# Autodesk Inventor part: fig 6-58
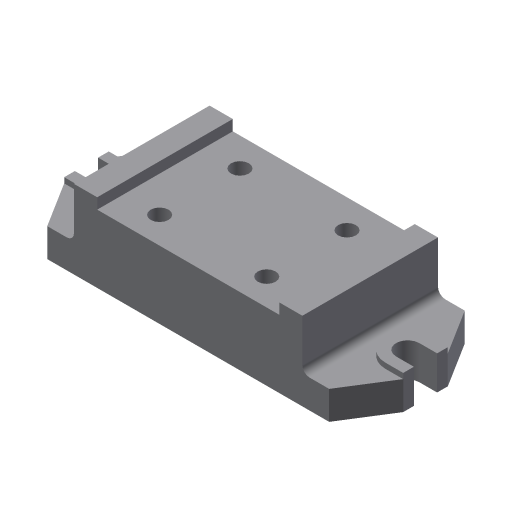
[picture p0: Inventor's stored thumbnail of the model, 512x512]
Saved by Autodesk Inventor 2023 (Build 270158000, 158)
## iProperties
Created: 2001-12
Part Number: fig 6-58
Document SubType Name: Modeling
Designer: Renu Muthoo
Density: 1 g/cm^3
Material: Generic
Appearance: Default
Control State: 0
Master: False
Checked Out: False
Shininess: 77.0
Angle Display Precision: 2
Document Length Units: 11269
Document Angle Units: 11279
Document Time Units: 11290
Document Mass Units: 11283
Document Length Units Precision: 3
Document Angle Units Precision: 2
Density: 0.0
Volumn: 0.0
Area: 0.0
PropertySet Name: Model Information
Author: Renu Muthoo
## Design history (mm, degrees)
sketch "Sketch3"
  geometry: L1 (-59.119, -24.322)-(-59.119, 19.678); L2 (-59.119, 19.678)-(-46.119, 19.678); L3 (-46.119, 19.678)-(-46.119, 13.678); L4 (-46.119, 13.678)-(55.881, 13.678); L5 (55.881, 13.678)-(55.881, 19.678); L6 (55.881, 19.678)-(68.881, 19.678); L7 (68.881, 19.678)-(68.881, -24.322); L8 (68.881, -24.322)-(-59.119, -24.322)
  constraints: 16 end point, 2 equal length
  dimensions: "d10" = 13 distance of L1.end L2.end; "d11" = 102 distance of L3.end L4.end; "d13" = 44 distance between parallel lines of L2 L8; "d14" = 6 distance of L2.end L3.end
extrude "Extrusion1" new body sketch "Sketch3" distance "d15" = 76; taper "d16" = 0 deg
sketch "Sketch4"
  geometry: L1 (0, 0)-(0, 76) reference; L2 (0, 76)-(-15, 76); L3 (-15, 76)-(-31, 50.5); L4 (-31, 50.5)-(-31, 44.5); L5 (-31, 44.5)-(-21, 44.5); L6 (-21, 31.5)-(-31, 31.5); L7 (-31, 31.5)-(-31, 25.5); L8 (-31, 25.5)-(-15, 0); L9 (-15, 0)-(0, 0); L10 (128, 76)-(0, 76) reference; L11 (0, 0)-(128, 0) reference; A1 r 6.5 centre (-21, 38) between (-21, 31.5) and (-21, 44.5)
  constraints: 16 end point, 4 equal length, 3 collinear, 3 parallel, 2 perpendicular, 2 point on circle, 2 tangent, 1 centre point
  dimensions: "d17" = 13 distance between parallel lines of L6 L5; "d18" = 25 distance of L3.end L7.end; "d19" = 10 distance of L6.start L6.end; "d20" = 15 distance of L8.end L1.start; "d21" = 16 horizontal distance of L7.end L8.end
extrude "Extrusion2" join sketch "Sketch4" distance "d22" = 16; taper "d23" = 0 deg
sketch "Sketch5"
  geometry: L1 (-159, 44.5)-(-159, 50.5) reference; L2 (-149, 44.5)-(-159, 44.5) reference; L3 (-159, 31.5)-(-149, 31.5) reference; L4 (-159, 25.5)-(-159, 31.5) reference; L5 (-159, 25.5)-(-149, 25.5); L6 (-149, 50.5)-(-159, 50.5); A1 r 6.5 centre (-149, 38) between (-149, 31.5) and (-149, 44.5) reference; A2 r 12.5 centre (-149, 38) between (-149, 25.5) and (-149, 50.5)
  constraints: 4 end point, 2 point on circle, 2 tangent, 1 centre point, 1 parallel, 1 perpendicular
extrude "Extrusion3" join sketch "Sketch5" distance "d24" = 19; taper "d25" = 0 deg
workplane "Work Plane1"
mirror "Mirror1"
fillet "Fillet1" dims "d27" = 4
sketch "Sketch6"
  geometry: L1 (0, 0)-(0, 76) reference; L2 (0, 0)-(102, 0) reference; 1 further point
  dimensions: "d28" = 20 distance from line of L1 point (20, 15); "d29" = 15 distance from line of L2 point (20, 15)
hole "Hole1" sketch "Sketch6" at (20, 15) diameter "d30" = 10; stored, may be unused: countersink angle "d34" = 82 deg, drill point angle "d36" = 118 deg; dims "d31" = 6, "d32" = 4, "d33" = 2, "d35" = 15
sketch "Sketch7"
  geometry: C1 r 5 at (20, 15) reference; 3 further points
  constraints: 4 other
pattern_linear "Rectangular Pattern2" dims "d45" = 45, "d48" = 60
body "Solid1"
other parameters: "d26" = -64
